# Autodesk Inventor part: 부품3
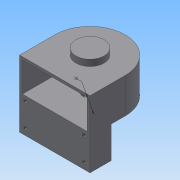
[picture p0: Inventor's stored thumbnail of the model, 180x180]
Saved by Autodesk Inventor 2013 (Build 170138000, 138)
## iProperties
Created: 2015-02
Part Number: 부품3
Material: 일반
Document SubType Name: Modeling
Designer: Administrator
Density: 1 g/cm^3
Author: Administrator
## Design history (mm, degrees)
sketch "스케치1"
  geometry: L1 (-50, 0)-(-50, -50); L2 (-50, -50)-(50, -50); L3 (50, -50)-(50, 0); A1 r 50 centre (0, 0) between (-50, 0) and (50, 0); 1 further point
  constraints: 6 end point, 2 point on circle, 2 tangent, 1 centre point, 1 coincident, 1 horizontal, 1 parallel, 1 vertical
  dimensions: "d0" = 100 diameter of A1; "d2" = 50 distance from line of L2 point (0, 0)
extrude "돌출1" new body sketch "스케치1" distance "d3" = 50; taper "d4" = 0 deg
sketch "스케치2"
  geometry: L1 (-50, 0)-(-50, -50) reference; L2 (-50, -50)-(50, -50) reference; L3 (50, -50)-(50, 0) reference; L4 (-50, -50)-(50, -50); L5 (50, -50)-(50, -20); L6 (50, -20)-(-50, -20); L7 (-50, -20)-(-50, -50); L8 (-50, -50)-(50, -20); L9 (50, -50)-(-50, -20); 1 further point
  constraints: 12 end point, 3 collinear, 2 midpoint, 2 parallel, 1 horizontal, 1 perpendicular
  dimensions: "d5" = 30 distance between parallel lines of L2 L6
extrude "돌출2" join sketch "스케치2" distance "d6" = 95; taper "d7" = 0 deg
sketch "스케치3"
  geometry: L1 (-50, -20)-(50, -20) reference; A1 r 50 centre (0, 0) between (50, 0) and (-50, 0) reference; A2 r 40 centre (0, 0) between (-34.641, -20) and (34.641, -20)
  constraints: 2 point on circle, 2 point on line, 1 centre point, 1 coincident
  dimensions: "d8" = 80 diameter of A2
extrude "돌출3" cut sketch "스케치3" stored distance "d10" = 95; taper "d11" = 0 deg
sketch "스케치4"
  geometry: C1 r 25 at (0, 0); A1 r 50 centre (0, 0) between (50, 0) and (-50, 0) reference
  constraints: 1 centre point, 1 coincident
  dimensions: "d12" = 50 diameter of C1
extrude "돌출4" join sketch "스케치4" distance "d14" = 10; taper "d15" = -20 deg
sketch "스케치5"
  geometry: C1 r 20 at (0, 0); A1 r 50 centre (0, 0) between (50, 0) and (-50, 0) reference
  constraints: 1 centre point, 1 coincident
  dimensions: "d16" = 40 diameter of C1
extrude "돌출5" join sketch "스케치5" distance "d18" = 9; taper "d19" = 0 deg
node "작업 평면1"
sketch "스케치7"
  geometry: L1 (-50, 0)-(-50, -50) reference; L2 (-50, -50)-(50, -50) reference; L3 (50, -50)-(50, 0) reference; L4 (46, 0)-(46, -50); L5 (-46, -50)-(-46, 0); L6 (-46, -50)-(46, -50); A1 r 50 centre (0, 0) between (50, 0) and (-50, 0) reference; A2 r 46 centre (0, 0) between (46, 0) and (-46, 0); 1 further point
  constraints: 6 end point, 2 point on circle, 2 point on line, 1 centre point, 1 collinear
  dimensions: "d21" = 4 radial gap between concentric circles of A1 A2; "d24" = 4 distance between parallel lines of L5 L1; "d25" = 4 distance between parallel lines of L3 L4
extrude "돌출6" cut sketch "스케치7" distance "d22" = 42; taper "d23" = 0 deg
hole "구멍1" diameter "d28" = 20; stored, may be unused: countersink angle "d32" = 90 deg, drill point angle "d34" = 0 deg; dims "d26" = 10, "d27" = 10, "d29" = 6, "d30" = 28, "d31" = 10, "d33" = 14
sketch "스케치8"
  geometry: A1 r 46 centre (0, 0) between (46, 0) and (-46, 0) reference; 1 further point
  constraints: 1 coincident
hole "구멍2" sketch "스케치8" at (0, 0) diameter "d35" = 20; stored, may be unused: countersink angle "d39" = 90 deg, drill point angle "d41" = 0 deg; dims "d36" = 6, "d37" = 28, "d38" = 8, "d40" = 10
sketch "스케치9"
  geometry: L1 (100, -95)-(0, -95) reference; L2 (91.75, -86)-(8.25, -86); L3 (8.25, -86)-(8.25, -53); L4 (8.25, -53)-(91.75, -53); L5 (91.75, -53)-(91.75, -86); L6 (91.75, -86)-(8.25, -53); L7 (8.25, -86)-(91.75, -53); 7 further points
  constraints: 12 end point, 4 coincident, 3 midpoint, 2 parallel, 1 horizontal, 1 perpendicular, 1 vertical alignment
  dimensions: "d42" = 33 distance of L2.end L3.end; "d44" = 83.5 distance of L2.start L2.end; "d45" = 9 distance between parallel lines of L2 L1
hole "구멍3" sketch "스케치9" at (8.25, -86), (8.25, -53), (91.75, -86), (91.75, -53) diameter "d46" = 5.134; stored, may be unused: countersink angle "d50" = 90 deg, drill point angle "d52" = 0 deg; dims "d47" = 10, "d48" = 28, "d49" = 8, "d51" = 13
sketch "스케치10"
  geometry: C1 r 14 at (0, 0) reference; C2 r 21.36 at (0, 0) reference; A1 r 18 centre (0, 0) between (0, 18) and (18, 0); 2 further points
  constraints: 4 point on circle, 2 horizontal alignment, 2 vertical alignment, 1 centre point, 1 coincident
  dimensions: "d53" = 36 diameter of A1
node "솔리드1"
other parameters: "d20" = -4
